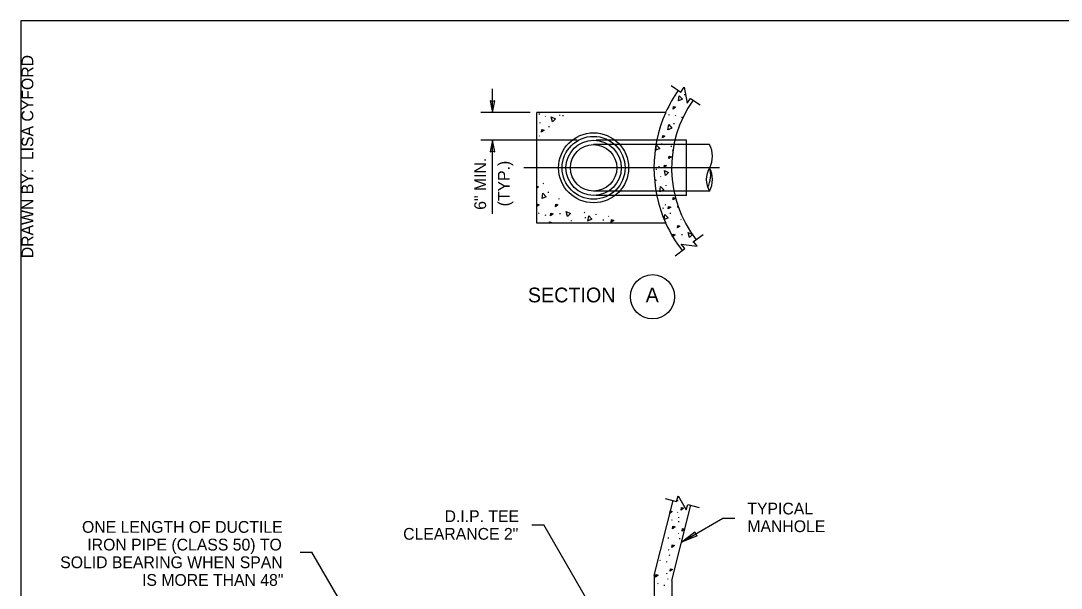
# Model space of a CAD drawing. Extents: x 99862 to 103151, y 100000 to 102076.
# Drawn here: x 99862 to 101274, y 101305 to 102076 of the extents above; entities that cross this region are included whole.
import ezdxf

# ---------------------------------------------------------------- set-up
doc = ezdxf.new("R2010")
doc.units = 0
for name, color, linetype in [('Level 1', 7, 'Continuous'), ('Level 15', 7, 'Continuous'), ('Level 17', 7, 'Continuous'), ('Level 19', 7, 'Continuous'), ('Level 20', 7, 'Continuous'), ('Level 27', 7, 'Continuous'), ('Level 62', 7, 'Continuous'), ('Level 9', 7, 'Continuous')]:
    doc.layers.add(name, color=color, linetype=linetype)

msp = doc.modelspace()

# ---------------------------------------------------------------- linework, layer by layer
at = {"layer": 'Level 1'}
for p, q in [((100748.6, 101907.5), (100639.5, 101907.5)), ((100749.9, 101913.5), (100643, 101913.5)), ((100796.7, 101907.5), (100748.6, 101907.5)), ((100765.4, 101913.5), (100749.9, 101913.5)), ((100765.4, 101838.5), (100765.4, 101913.5)), ((100810.3, 101876), (100544.9, 101876)), ((100748.6, 101844.5), (100639.5, 101844.5)), ((100749.9, 101838.5), (100643, 101838.5)), ((100796.7, 101844.5), (100748.6, 101844.5)), ((100765.4, 101838.5), (100749.9, 101838.5)), ((100721.8, 101322.5), (100747.3, 101424.5)), ((100745.8, 101316), (100771.3, 101418)), ((100721.8, 101322.5), (100721.8, 101276)), ((100745.8, 101316), (100745.8, 101283))]:
    msp.add_line(p, q, dxfattribs=at)
msp.add_lwpolyline([(99862, 99999.5), (103151, 99999.5), (103151, 102075.5), (99862, 102075.5)], close=True, dxfattribs=at)
for radius in [47.5, 42.7, 37.5, 31.5]:
    msp.add_circle((100639.5, 101876), radius, dxfattribs=at)
for centre, radius, start, end in [((100905.2, 101876), 183.8, 145.0678, 155.6578), ((100905.2, 101876), 159.8, 144.903, 217.6415), ((100769.4, 101891.7), 31.5, 330, 30), ((100823.9, 101860.2), 31.5, 150, 210), ((100764.7, 101865.5), 33.7, 331.7011, 18.1584), ((100769.4, 101860.2), 31.5, 330, 30), ((100905.2, 101876), 183.8, 204.2717, 217.6359)]:
    msp.add_arc(centre, radius, start, end, dxfattribs=at)
at = {"layer": 'Level 15'}
for p, q in [((100502.3, 101951), (100502.3, 101983)), ((100553.6, 101951), (100486.3, 101951)), ((100617.1, 101913.5), (100486.3, 101913.5)), ((100502.3, 101813.4), (100502.3, 101913.5)), ((100758.8, 101367.9), (100815.1, 101400.4)), ((100815.1, 101400.4), (100831.1, 101400.4)), ((100555.8, 101391.3), (100571.8, 101391.3)), ((100638.3, 101276), (100571.8, 101391.3)), ((100241.1, 101354.5), (100257.1, 101354.5)), ((100299.4, 101281.2), (100257.1, 101354.5))]:
    msp.add_line(p, q, dxfattribs=at)
for points in [[(100744.8, 101987.8), (100758.1, 101978.8), (100762.4, 101985.3), (100766.7, 101963.8), (100771, 101970.2), (100784.3, 101961.3)], [(100750.4, 101756.6), (100763.1, 101766.4), (100758.4, 101772.5), (100780.1, 101769.7), (100775.3, 101775.8), (100788, 101785.6)], [(100736.8, 101427.3), (100752.2, 101423.2), (100754.3, 101430.6), (100765.2, 101411.7), (100767.2, 101419.1), (100782.6, 101415)]]:
    msp.add_lwpolyline(points, dxfattribs=at)
for points in [[(100502.3, 101951), (100505.4, 101966.7), (100502.3, 101966), (100499.3, 101966.7)], [(100502.3, 101913.5), (100499.3, 101897.8), (100502.3, 101898.5), (100505.4, 101897.8)], [(100758.8, 101367.9), (100777.1, 101381.9), (100777.7, 101378.7), (100780.1, 101376.7)]]:
    msp.add_lwpolyline(points, close=True, dxfattribs=at)
at = {"layer": 'Level 17'}
for p, q in [((100562.3, 101801), (100562.3, 101951)), ((100737.5, 101951), (100562.3, 101951)), ((100737.5, 101801), (100562.3, 101801)), ((100581.5, 101801.5), (100581.5, 101801)), ((100615.6, 101801.5), (100615.5, 101801))]:
    msp.add_line(p, q, dxfattribs=at)
msp.add_arc((100905.2, 101876), 183.8, 155.9149, 204.0851, dxfattribs=at)
at = {"layer": 'Level 19'}
for p, q in [((100763.2, 101974.6), (100763.2, 101975.8)), ((100573.6, 101946.2), (100574.3, 101945.7)), ((100593.7, 101946.8), (100593.7, 101948)), ((100598.3, 101946.1), (100598.4, 101947.3)), ((100741.3, 101948.2), (100742, 101947.7)), ((100750, 101947.4), (100750.5, 101946.4)), ((100759.5, 101943.9), (100759.6, 101945.1)), ((100566.9, 101936.5), (100566.9, 101937.7)), ((100579.1, 101931.3), (100579.2, 101932.5)), ((100748.9, 101935.4), (100748.9, 101936.6)), ((100565.5, 101919.6), (100566.2, 101919.1)), ((100732.2, 101907.7), (100732.3, 101908.9)), ((100735.6, 101908.2), (100736.1, 101907.2)), ((100745.2, 101904.6), (100745.3, 101905.9)), ((100746.1, 101900), (100746.9, 101899.5)), ((100724.8, 101873.3), (100724.9, 101874.5)), ((100728.6, 101876.9), (100728.7, 101878.2)), ((100730.2, 101864.2), (100730.9, 101863.7)), ((100570.6, 101855), (100571.3, 101854.5)), ((100737.8, 101851.4), (100737.9, 101852.6)), ((100578.1, 101842.2), (100578.2, 101843.4)), ((100592, 101834.5), (100592.7, 101833.9)), ((100734.1, 101820.7), (100734.2, 101821.9)), ((100736.2, 101826.4), (100736.9, 101825.9)), ((100753.6, 101822.3), (100753.7, 101823.5)), ((100564.9, 101815), (100565.4, 101814)), ((100574.4, 101811.4), (100574.5, 101812.6)), ((100593.9, 101813.1), (100594, 101814.3)), ((100609.5, 101803.4), (100609.6, 101804.6)), ((100626.7, 101815.6), (100627.4, 101815.1)), ((100628.6, 101807.6), (100628.7, 101808.8)), ((100643, 101812), (100643, 101813.2)), ((100652.7, 101804.7), (100652.8, 101805.9)), ((100659.5, 101810.2), (100660.2, 101809.7)), ((100743.8, 101813.6), (100743.9, 101814.8)), ((100757.7, 101805.9), (100758.4, 101805.3)), ((100759.6, 101784.5), (100759.7, 101785.7)), ((100775.2, 101774.8), (100775.3, 101776)), ((100753.6, 101423.7), (100753.6, 101424.9)), ((100753.2, 101408.7), (100753.9, 101408.2)), ((100745.4, 101398.6), (100745.9, 101397.6)), ((100755, 101395), (100755.1, 101396.3)), ((100755.1, 101400.7), (100755.2, 101401.9)), ((100741.1, 101372.9), (100741.2, 101374.1)), ((100754.6, 101380.1), (100755.3, 101379.6)), ((100756.5, 101372.1), (100756.6, 101373.3)), ((100740.8, 101357.9), (100741.5, 101357.4)), ((100729.3, 101344.1), (100729.8, 101343.1)), ((100738.8, 101340.6), (100738.9, 101341.8)), ((100742.7, 101349.9), (100742.8, 101351.1)), ((100738.5, 101325.6), (100739.2, 101325.1)), ((100726.1, 101312.3), (100726.6, 101311.3)), ((100735.6, 101308.7), (100735.7, 101310)), ((100740.4, 101317.6), (100740.5, 101318.8))]:
    msp.add_line(p, q, dxfattribs=at)
for points in [[(100754.7, 101966.7), (100755.7, 101973.8), (100760.2, 101969.3), (100754.9, 101966.8)], [(100747.4, 101955.7), (100747.8, 101959.2), (100750.7, 101958.3), (100747.4, 101955.7)], [(100583.6, 101938.2), (100582.1, 101945.2), (100587.8, 101942.4), (100583.7, 101938.3)], [(100740.4, 101927.5), (100741.4, 101934.6), (100745.9, 101930), (100740.5, 101927.6)], [(100568.8, 101924.4), (100569.2, 101927.8), (100572.2, 101926.9), (100568.8, 101924.4)], [(100733.1, 101916.5), (100733.5, 101920), (100736.4, 101919.1), (100733.1, 101916.5)], [(100723.8, 101899.8), (100724.8, 101906.9), (100729.3, 101902.3), (100723.9, 101899.9)], [(100741.8, 101888.6), (100742.2, 101892), (100745.1, 101891.1), (100741.8, 101888.6)], [(100735.2, 101876.4), (100735.6, 101879.8), (100738.6, 101878.9), (100735.2, 101876.4)], [(100737, 101865.4), (100735.5, 101872.4), (100741.2, 101869.6), (100737.1, 101865.5)], [(100562.3, 101850.9), (100564.9, 101850.1), (100562.3, 101848.2)], [(100722, 101860.1), (100724.5, 101859.3), (100722.4, 101857.7)], [(100729.4, 101843.5), (100730.3, 101850.6), (100734.8, 101846), (100729.5, 101843.6)], [(100569.7, 101834.3), (100570.7, 101841.4), (100575.1, 101836.8), (100569.8, 101834.3)], [(100747.4, 101832.3), (100747.7, 101835.7), (100750.7, 101834.8), (100747.4, 101832.3)], [(100562.4, 101823.3), (100562.7, 101826.7), (100565.7, 101825.8), (100562.4, 101823.3)], [(100587.7, 101823.1), (100588, 101826.5), (100591, 101825.6), (100587.7, 101823.1)], [(100740.8, 101820.1), (100741.1, 101823.5), (100744.1, 101822.6), (100740.8, 101820.1)], [(100581.1, 101810.9), (100581.5, 101814.3), (100584.4, 101813.4), (100581.1, 101810.9)], [(100603.9, 101809.9), (100602.4, 101816.9), (100608.1, 101814.1), (100604, 101810)], [(100631.8, 101803.7), (100632.8, 101810.8), (100637.3, 101806.3), (100631.9, 101803.8)], [(100663.5, 101802.2), (100663.9, 101805.7), (100666.8, 101804.7), (100663.5, 101802.2)], [(100735.4, 101805.7), (100736.3, 101812.8), (100740.8, 101808.2), (100735.5, 101805.7)], [(100579.3, 101801), (100579.5, 101802.7), (100582.5, 101801.8), (100581.4, 101801)], [(100753.4, 101794.4), (100753.7, 101797.9), (100756.7, 101797), (100753.4, 101794.4)], [(100746.8, 101782.3), (100747.1, 101785.7), (100750.1, 101784.8), (100746.8, 101782.3)], [(100769.5, 101781.3), (100768, 101788.3), (100773.8, 101785.5), (100769.6, 101781.4)], [(100742.9, 101406.9), (100743.3, 101410.3), (100746.2, 101409.4), (100742.9, 101406.9)], [(100758.3, 101411.5), (100758.6, 101414.9), (100761.6, 101414), (100758.3, 101411.5)], [(100746.7, 101386.2), (100747, 101389.7), (100750, 101388.7), (100746.7, 101386.2)], [(100759.7, 101382.9), (100760, 101386.3), (100763, 101385.4), (100759.7, 101382.9)], [(100745.8, 101360.7), (100746.2, 101364.1), (100749.1, 101363.2), (100745.8, 101360.7)], [(100723.5, 101320.6), (100723.9, 101324.1), (100726.9, 101323.2), (100723.5, 101320.6)], [(100743.5, 101328.4), (100743.9, 101331.8), (100746.8, 101330.9), (100743.5, 101328.4)]]:
    msp.add_lwpolyline(points, dxfattribs=at)
at = {"layer": 'Level 27'}
msp.add_line((100565.8, 101948.4), (100566.3, 101949.6), dxfattribs=at)
at = {"layer": 'Level 9'}
msp.add_circle((100719.5, 101701), 30, dxfattribs=at)

# ---------------------------------------------------------------- texts
at = {"layer": 'Level 20'}
for s, rotation, p in [('6" MIN.', 90, (100493.6, 101819)), ('(TYP.)', 90, (100525.6, 101823.7)), ('TYPICAL', 360, (100848.2, 101405.5)), ('MANHOLE', 360, (100848.2, 101381.5))]:
    msp.add_text(s, height=16, rotation=rotation, dxfattribs=at).set_placement(p)
for s, height, p in [('SECTION', 20, (100550.3, 101693.4)), ('A', 20, (100710.2, 101693.4)), ('D.I.P. TEE', 16, (100437.2, 101395.2)), ('ONE LENGTH OF DUCTILE', 16, (99945.1, 101380.6)), ('CLEARANCE 2"', 16, (100381, 101371.2)), ('IRON PIPE (CLASS 50) TO', 16, (99952.3, 101356.6)), ('SOLID BEARING WHEN SPAN', 16, (99915.5, 101332.6)), ('IS MORE THAN 48"', 16, (100026.6, 101308.6))]:
    msp.add_text(s, height=height, dxfattribs=at).set_placement(p)
at = {"layer": 'Level 62'}
msp.add_text('DRAWN BY:  LISA CYFORD', height=16, rotation=90, dxfattribs=at).set_placement((99879, 101753.3))

doc.saveas('drawing.dxf')
